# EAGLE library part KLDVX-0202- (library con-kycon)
Power Jack, Vertical, PCB Mount, 2.0 mm, 2.5 mm, 3.0 mm Center Pin Source: KLDVX-0202x.pdf
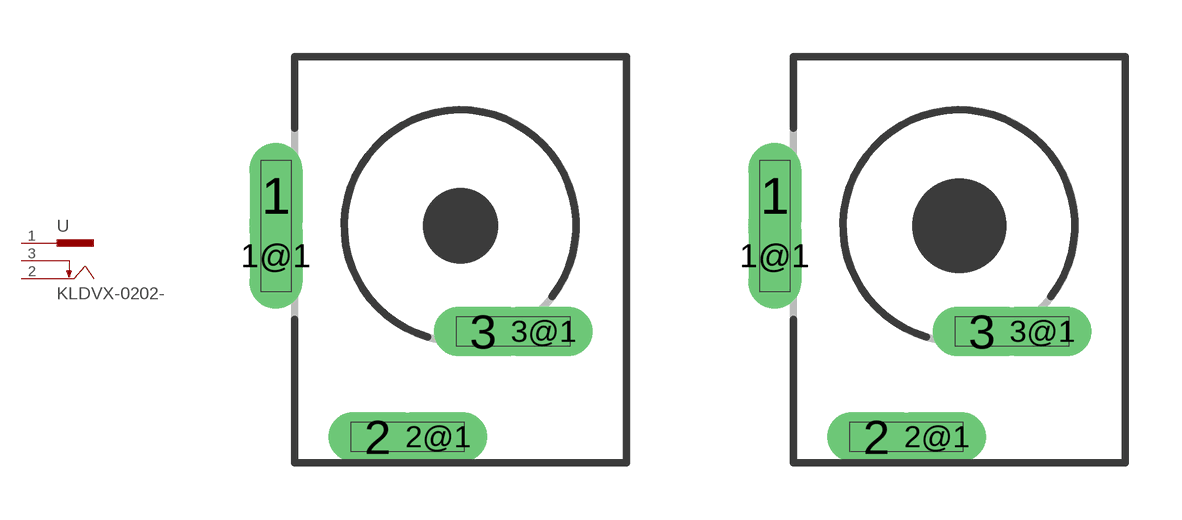
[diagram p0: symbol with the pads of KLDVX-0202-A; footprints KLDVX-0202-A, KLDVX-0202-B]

Designator prefix -

## KLDVX-0202-A (OC_FARNELL: unknown; OC_NEWARK: unknown)  [KLDVX-0202-A]
1  1  pas
1@1  1  pas
2  2  pas
2@1  2  pas
3  3  pas
3@1  3  pas

## KLDVX-0202-B (OC_FARNELL: unknown; OC_NEWARK: unknown)  [KLDVX-0202-B]
Pads as for KLDVX-0202-A

## KLDVX-0202-C (OC_FARNELL: unknown; OC_NEWARK: unknown)  [KLDVX-0202-C]
Pads as for KLDVX-0202-A

## Footprint KLDVX-0202-A (pad centres in mm)
Power Jack, Vertical, PCB Mount, 2.0 mm Center Pin Source: KLDVX-0202x.pdf
drill 0.8 pad 1.4 long: 1 -4.9,0.8; 1@1 -4.9,-0.8
drill 0.8 pad 1.3 long: 2 -2.2,-5.6; 2@1 -0.6,-5.6; 3 0.6,-2.8; 3@1 2.2,-2.8

## Footprint KLDVX-0202-B (pad centres in mm)
Power Jack, Vertical, PCB Mount, 2.5 mm Center Pin Source: KLDVX-0202x.pdf
drill 0.8 pad 1.4 long: 1 -4.9,0.8; 1@1 -4.9,-0.8
drill 0.8 pad 1.3 long: 2 -2.2,-5.6; 2@1 -0.6,-5.6; 3 0.6,-2.8; 3@1 2.2,-2.8

## Footprint KLDVX-0202-C (pad centres in mm)
Power Jack, Vertical, PCB Mount, 3.0 mm Center Pin Source: KLDVX-0202x.pdf
drill 0.8 pad 1.4 long: 1 -4.9,0.8; 1@1 -4.9,-0.8
drill 0.8 pad 1.3 long: 2 -2.2,-5.6; 2@1 -0.6,-5.6; 3 0.6,-2.8; 3@1 2.2,-2.8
